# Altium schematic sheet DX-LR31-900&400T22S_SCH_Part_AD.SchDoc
size A4
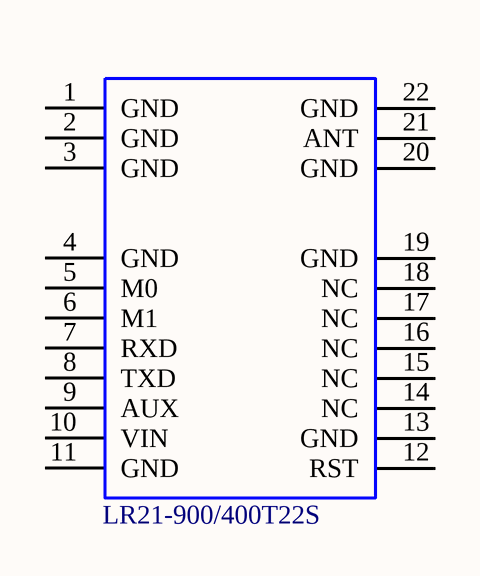
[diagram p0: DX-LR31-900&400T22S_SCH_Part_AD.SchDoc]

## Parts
?  LR21-900/400T22S  [PE220-400M22S]

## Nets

Not connected (* = marked no-connect by the designer): ? 1(GND) 2(GND) 3(GND) 4(GND) 5(M0) 6(M1) 7(RXD) 8(TXD) 9(AUX) 10(VIN) 11(GND) 12(RST) 13(GND) 14(NC) 15(NC) 16(NC) 17(NC) 18(NC) 19(GND) 20(GND) 21(ANT) 22(GND)

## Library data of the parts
? = LR31-900/400T22S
